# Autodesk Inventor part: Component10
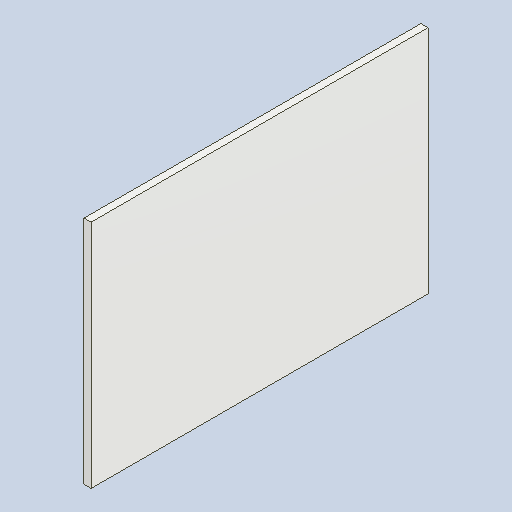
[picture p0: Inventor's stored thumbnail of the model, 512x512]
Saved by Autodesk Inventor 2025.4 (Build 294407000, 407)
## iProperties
Created: 2026-06
Part Number: Component10
Material: Generic
Document SubType Name: Modeling
Designer: AdminForWorker
Density: 1 g/cm^3
Appearance: Default
Title: Component10
Author: AdminForWorker
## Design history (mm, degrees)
feature "Body1"
body "Solid1"
